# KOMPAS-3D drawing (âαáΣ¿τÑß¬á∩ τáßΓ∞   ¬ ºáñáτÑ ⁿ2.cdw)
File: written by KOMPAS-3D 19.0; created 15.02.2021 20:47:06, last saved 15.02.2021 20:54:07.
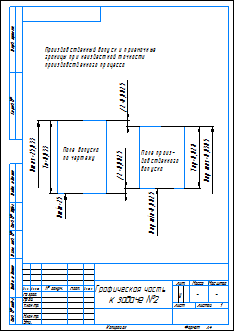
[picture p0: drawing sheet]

Sheet 1: A4, portrait

Document properties: Автор: Юрий; Полное имя файла: C:\Users\Юрий\Desktop\метрология сироп\Графическая часть   к задаче №2.cdw

Title block, sheet 1: Наименование: Графическая часть / к задаче №2; Количество листов документа: 1; Форматы листов документа: A4; Литера: у

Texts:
  Производственный допуск и приемочные
  границы при неизвестной точности
  производственного процесса
  Поле допуска
  по чертежу
  Поле произ-
  водственного
  допуска
  Тпр=
  Dпр max=0,0305
  Dпр min=0,0025
Dimensions and other numbers on the sheet: 0,028; 2; 1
